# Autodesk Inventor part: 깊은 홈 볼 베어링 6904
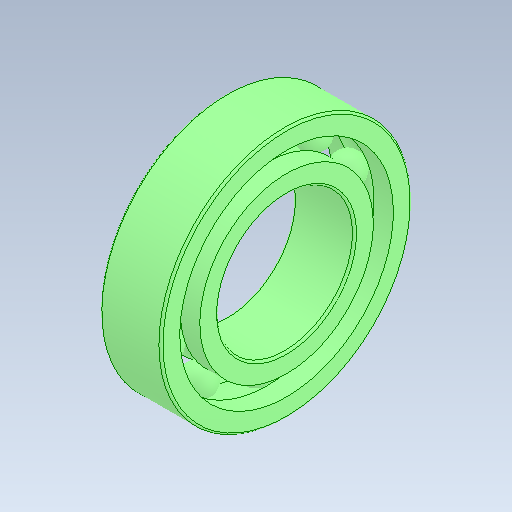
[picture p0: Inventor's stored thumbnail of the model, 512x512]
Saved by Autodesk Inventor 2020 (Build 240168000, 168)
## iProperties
Created: 2024-08
Part Number: 깊은 홈 볼 베어링 6904
Material: 강철, 연강
Description: 깊은 그루브 볼 베어링
Document SubType Name: Modeling
Designer: oem
Density: 7.85 g/cm^3
Appearance: 기본값
Author: jhkim
Sending System: Autodesk Inventor 2025
Preprocessor: ST-DEVELOPER v20
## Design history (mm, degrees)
node "깊은 홈 볼 베어링 69041"
node "솔리드1"
node "솔리드2"
node "솔리드3"
node "솔리드4"
node "솔리드5"
node "솔리드6"
node "솔리드7"
node "솔리드8"
node "솔리드9"
node "솔리드10"
node "솔리드11"
node "솔리드12"
body "Solid1"
node "Solid1:1"
node "Solid1:2"
node "Solid1:3"
node "Solid1:4"
node "Solid1:5"
node "Solid1:6"
node "Solid1:7"
node "Solid1:8"
node "Solid1:9"
node "Solid1:10"
node "Solid1:11"
